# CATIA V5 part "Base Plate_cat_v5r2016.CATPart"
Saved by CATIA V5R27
Part number: Base Plate
Bounding box of the stored display mesh (mm): x -10 to 10, y 0 to 144, z 0 to 6
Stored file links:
  E:\_Deepak\2017_Deepak\CATIA\Resources\Tutorial Files\Tutorials\c13_catia_v5_6r2016_tut\c13tut2\c13tut02.CATParts\Base Plate_cat_v5r2016.CATPart
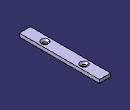
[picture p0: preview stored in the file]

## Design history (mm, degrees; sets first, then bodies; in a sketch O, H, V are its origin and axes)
Body1 (main body)
  Sketch1 on zx-plane, origin (0, 0, 0), H (-1, 0, 0), V (0, 0, 1)
    point P1 (-10, 0)
    line L1 (-10, 0) -> (10, 0)
    line L2 (10, 0) -> (10, 6)
    line L3 (10, 6) -> (-10, 6)
    line L4 (-10, 6) -> (-10, 0)
    length L3 = 20
    length L2 = 6
    distance V L2 = 10
    coincidence: P1 H
    horizontal: L1 H, L3 H
    vertical: L2 V, L4 V
  Pad1: profile Sketch1, direction (0, 1, 0), length 144
  Sketch2 on face of Pad1, origin (-6.0071, 115.251, 6), H (1, 0, 0), V (0, 1, 0)
    point P1 (6.0071, -9.251)
    reference projected line E1 (-3.9929, -115.251) -> (-3.9929, 28.749) from edge of Pad1
    reference projected line E2 (16.0071, 28.749) -> (-3.9929, 28.749) from edge of Pad1
    distance E1 P1 = 10
    distance E2 P1 = 38
  Hole1: placed by Sketch2, at (0, 106, 6) direction (0, 0, -1), diameter 7, through (limit type 6), countersink depth 3, countersink angle 90
  RectPattern1: of Hole1, direction 1 instances 2, spacing 70, along edge of Pad1 reversed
